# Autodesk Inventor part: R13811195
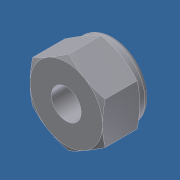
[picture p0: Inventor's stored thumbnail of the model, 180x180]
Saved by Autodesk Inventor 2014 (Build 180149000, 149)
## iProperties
Shininess: 20.0
Length Units: 11272
Angle Units: 11279
Time Units: 11290
Mass Units: 11286
Length Display Precision: 3
Angle Display Precision: 2
Company: Autodesk, Inc.
Created: 2001-10
Part Number: R13811195
Material: Steel, Mild A-36
Description: Lock-nut; 5/8~11
Document SubType Name: Modeling
Designer: Autodesk, Inc.
Density: 7.86 g/cm^3
Mass: 47.0576 g
Surface Area: 29.4927 cm^2
Volume: 5.98697 cm^3
Appearance: Yellow Zinc
Density: 8.94
Volumn: 1.3062604850048036
Area: 10.612586411503024
PropertySet Name: Model Information
Control State: 0
Master: False
Checked Out: True
Last Check In By: JT
Last Check In Date: 2003-06-20
MODEL - 1: ---
MODEL - 2: ---
RAW MATERIAL: --------
SCALE:: 1=??
SIZE: 00 x 00 x 00
SUB-ASSY - 1: ------
SUB-ASSY - 1 - QUA: 1
SUB-ASSY - 2: ------
SUB-ASSY - 2 - QUA: 1
SYM. TO:: N/A
TEMPLATE CREATION: -- / __-__-__
Author: Autodesk, Inc.
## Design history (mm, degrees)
derived "Lock-nut.ipt"
body "Solid1"
tag "TaggingFeature2"
feature "Solid1::Lock-nut.ipt" dims "ScaleForDerivedMember" = 10
